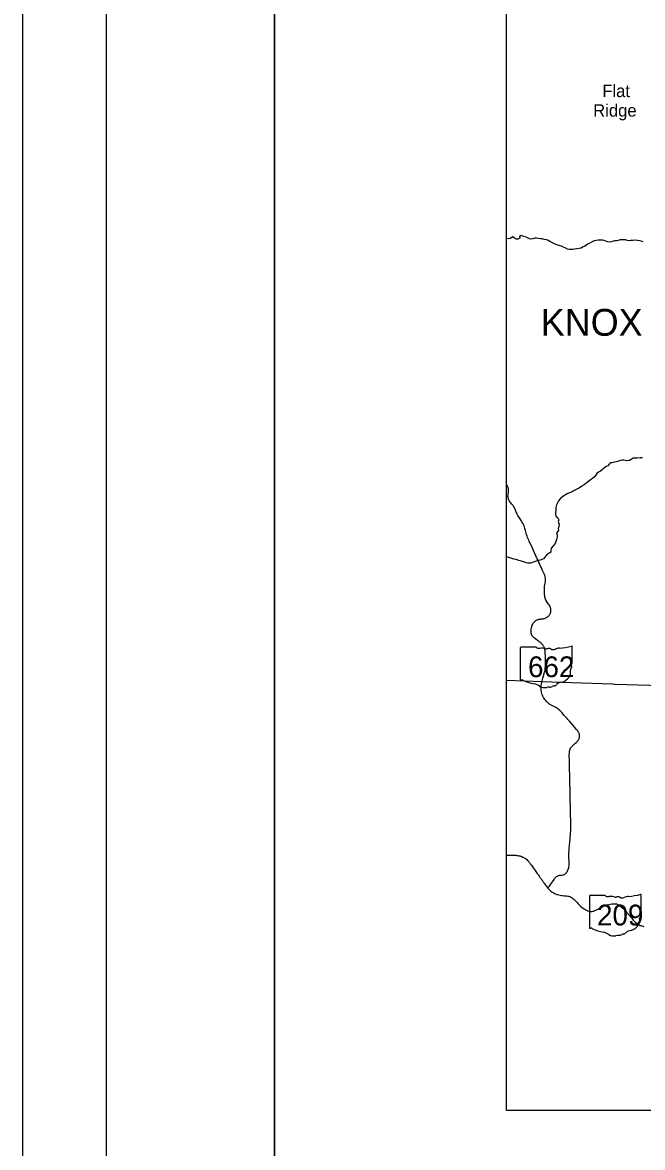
# Model space of a CAD drawing. Extents: x -12.1 to 34, y 0 to 22.
# Drawn here: x 0 to 3.69, y 10.76 to 17.46 of the extents above; entities that cross this region are included whole.
import ezdxf

# ---------------------------------------------------------------- set-up
doc = ezdxf.new("R2010")
doc.units = 0
for name, color, linetype in [('GM_X_Minor_River', 7, 'Continuous'), ('GM_X_State_Location', 7, 'Continuous'), ('GM_X_State_Route', 7, 'Continuous'), ('GM_X_State_Shield', 7, 'Continuous'), ('GM_X_Township', 7, 'Continuous'), ('GM_X_Township_Text', 7, 'Continuous'), ('GM_X_Unincorporated_Text', 7, 'Continuous'), ('SH_Border', 7, 'Continuous'), ('SH_Cut_Line', 7, 'Continuous'), ('SH_Text', 7, 'Continuous')]:
    doc.layers.add(name, color=color, linetype=linetype)

msp = doc.modelspace()

# ---------------------------------------------------------------- linework, layer by layer
at = {"layer": 'GM_X_Minor_River'}
for points in [[(3.6955, 16.1496), (3.6831, 16.153), (3.6742, 16.1565), (3.6617, 16.1581), (3.6454, 16.1597), (3.633, 16.1585), (3.6216, 16.157), (3.6121, 16.1558), (3.6, 16.1586), (3.5911, 16.161), (3.5815, 16.1626), (3.5673, 16.1625), (3.5577, 16.1613), (3.5457, 16.1577), (3.5358, 16.1565), (3.5266, 16.1553), (3.5152, 16.1534), (3.5057, 16.1505), (3.494, 16.1479), (3.4851, 16.1499), (3.473, 16.1537), (3.4623, 16.1572), (3.4531, 16.1588), (3.4396, 16.1601), (3.4265, 16.1593), (3.4141, 16.1574), (3.4024, 16.1548), (3.3908, 16.15), (3.378, 16.1428), (3.3682, 16.1377), (3.3565, 16.1301), (3.347, 16.1244), (3.3343, 16.1178), (3.3251, 16.1128), (3.3134, 16.1098), (3.2851, 16.106), (3.2755, 16.1045), (3.2642, 16.1036), (3.2539, 16.1046), (3.245, 16.1066), (3.2311, 16.1132), (3.2201, 16.1185), (3.209, 16.1233), (3.1998, 16.1268), (3.1894, 16.1295), (3.1805, 16.1319), (3.1713, 16.1357), (3.1624, 16.1402), (3.1517, 16.1462), (3.1399, 16.1524), (3.131, 16.157), (3.1193, 16.1615), (3.1057, 16.1645), (3.0926, 16.1669), (3.0834, 16.1682), (3.0716, 16.1699), (3.0592, 16.1708), (3.05, 16.1714), (3.0376, 16.1681), (3.0263, 16.1662), (3.0174, 16.1672), (3.0031, 16.1752), (2.9914, 16.1801), (2.9793, 16.1842), (2.9679, 16.1866), (2.958, 16.1815), (2.9606, 16.1716), (2.9489, 16.1654), (2.9379, 16.1664), (2.9265, 16.1741), (2.9169, 16.1786), (2.9056, 16.1696), (2.8929, 16.1684), (2.8822, 16.1694), (2.8817, 16.1698)], [(3.5005, 14.8331), (3.4945, 14.8275), (3.4839, 14.8168), (3.4744, 14.8117), (3.4617, 14.802), (3.4519, 14.7937), (3.4399, 14.7847), (3.429, 14.7782), (3.4198, 14.7703), (3.4131, 14.7613), (3.4047, 14.7499), (3.3938, 14.7402), (3.3818, 14.7319), (3.3692, 14.7222), (3.3434, 14.7027), (3.3293, 14.694), (3.3152, 14.6857), (3.3, 14.6778), (3.2849, 14.6691), (3.2722, 14.6622), (3.2559, 14.6556), (3.2428, 14.6491), (3.233, 14.6433), (3.2238, 14.6386), (3.2121, 14.6303), (3.2009, 14.6192), (3.1907, 14.607), (3.1841, 14.5963), (3.1792, 14.5831), (3.1758, 14.5681), (3.1742, 14.5532), (3.1725, 14.5397), (3.1723, 14.5304), (3.1749, 14.5169), (3.186, 14.5064), (3.1918, 14.4947), (3.1897, 14.484), (3.1938, 14.467), (3.1918, 14.4546), (3.188, 14.4425), (3.1902, 14.4311), (3.1797, 14.4178), (3.1837, 14.4076), (3.1838, 14.3969), (3.1807, 14.3852), (3.1787, 14.3756), (3.1742, 14.3652), (3.1704, 14.3538), (3.1605, 14.342), (3.1465, 14.3251), (3.1448, 14.3134), (3.1442, 14.3013), (3.1329, 14.2948), (3.1223, 14.2908), (3.1146, 14.2804), (3.1094, 14.2715), (3.1006, 14.2621), (3.0907, 14.2574), (3.0812, 14.2541), (3.0684, 14.2522), (3.0575, 14.2482), (3.0458, 14.2438), (3.0352, 14.2409), (3.0242, 14.2375), (3.0086, 14.2374), (2.9944, 14.2404), (2.9709, 14.248), (2.9556, 14.2521), (2.9396, 14.2577), (2.925, 14.2611), (2.9133, 14.2649), (2.9012, 14.2686), (2.8887, 14.2724), (2.8817, 14.2737)], [(3.691, 14.8643), (3.6761, 14.8635), (3.6591, 14.8622), (3.6481, 14.8614), (3.6343, 14.8609), (3.6234, 14.8537), (3.6128, 14.8483), (3.6022, 14.8457), (3.5887, 14.8477), (3.5787, 14.8501), (3.5695, 14.8493), (3.5596, 14.847), (3.5486, 14.8437), (3.5337, 14.84), (3.5221, 14.8378), (3.5086, 14.8344), (3.5005, 14.8331)]]:
    msp.add_lwpolyline(points, dxfattribs=at)
at = {"layer": 'GM_X_State_Route'}
for points in [[(3.0917, 13.5312), (3.093, 13.5365), (3.0973, 13.551), (3.1017, 13.5655), (3.1053, 13.579), (3.1077, 13.5886), (3.1085, 13.5922), (3.1105, 13.602), (3.1117, 13.6091), (3.1121, 13.6119), (3.1131, 13.6221), (3.1136, 13.629), (3.1138, 13.6325), (3.114, 13.6406), (3.1138, 13.6569), (3.1132, 13.6675), (3.1126, 13.6865), (3.1119, 13.697), (3.1114, 13.7085), (3.1109, 13.7137), (3.1102, 13.7202), (3.1096, 13.7242), (3.1088, 13.7279), (3.1081, 13.7303), (3.1073, 13.7324), (3.1061, 13.7351), (3.1051, 13.7372), (3.1037, 13.7397), (3.102, 13.7429), (3.1003, 13.7454), (3.0983, 13.748), (3.0955, 13.7514), (3.0925, 13.7548), (3.0882, 13.7591), (3.0846, 13.7622), (3.0801, 13.7658), (3.0763, 13.7686), (3.073, 13.7712), (3.0659, 13.7764), (3.0556, 13.7838), (3.0486, 13.7893), (3.0431, 13.7941), (3.0394, 13.7978), (3.0367, 13.8012), (3.035, 13.8034), (3.0342, 13.8046), (3.0331, 13.8062), (3.0322, 13.8082), (3.0311, 13.8105), (3.0304, 13.8122), (3.0295, 13.8149), (3.0289, 13.8169), (3.0282, 13.8203), (3.0274, 13.825), (3.0271, 13.8295), (3.027, 13.8326), (3.0273, 13.8361), (3.0276, 13.8409), (3.0285, 13.8466), (3.0296, 13.8521), (3.0312, 13.858), (3.0329, 13.8632), (3.0355, 13.8686), (3.0383, 13.8741), (3.0409, 13.8783), (3.0442, 13.883), (3.047, 13.8866), (3.05, 13.8897), (3.0517, 13.8913), (3.0535, 13.8928), (3.0561, 13.8948), (3.0587, 13.8965), (3.062, 13.8984), (3.0655, 13.9), (3.0696, 13.9013), (3.0732, 13.9021), (3.0761, 13.9028), (3.0797, 13.9034), (3.0831, 13.904), (3.0865, 13.9044), (3.0905, 13.9046), (3.0944, 13.9051), (3.0986, 13.9057), (3.1029, 13.9065), (3.107, 13.9074), (3.1114, 13.9087), (3.1159, 13.9108), (3.1197, 13.9126), (3.1231, 13.9147), (3.1256, 13.9164), (3.128, 13.9185), (3.1306, 13.9207), (3.1328, 13.9227), (3.1351, 13.9254), (3.1369, 13.928), (3.1388, 13.9307), (3.1411, 13.9348), (3.1438, 13.9416), (3.1446, 13.9447), (3.1454, 13.9486), (3.1456, 13.9506), (3.1457, 13.9524), (3.1457, 13.9569), (3.1452, 13.9616), (3.1443, 13.9663), (3.1428, 13.9714), (3.141, 13.9762), (3.1382, 13.9824), (3.1346, 13.9885), (3.1301, 13.9951), (3.126, 14.0006), (3.1195, 14.0093), (3.1157, 14.0155), (3.1125, 14.0229), (3.1111, 14.0276), (3.1098, 14.0332), (3.1087, 14.0411), (3.1079, 14.0481), (3.1073, 14.0566), (3.1069, 14.0672), (3.1069, 14.0805), (3.1073, 14.0909), (3.1078, 14.0972), (3.1094, 14.1097), (3.1107, 14.1162), (3.1128, 14.1264), (3.1138, 14.1336), (3.114, 14.1371), (3.1137, 14.1434), (3.1135, 14.1458), (3.1123, 14.1525), (3.1111, 14.1565), (3.109, 14.1632), (3.1065, 14.1695), (3.1027, 14.1777), (3.0954, 14.1938), (3.0914, 14.2023), (3.0889, 14.2084), (3.0844, 14.2184), (3.0822, 14.2231), (3.0796, 14.2286), (3.0779, 14.2326), (3.0774, 14.2336), (3.074, 14.2409), (3.0714, 14.2467), (3.069, 14.2519), (3.0669, 14.2567), (3.0644, 14.2619), (3.0564, 14.28), (3.048, 14.2986), (3.036, 14.3251), (3.0311, 14.3357), (3.0272, 14.3435), (3.017, 14.3655), (3.0137, 14.3728), (3.0101, 14.3811), (3.007, 14.389), (3.004, 14.3973), (3.0007, 14.4077), (2.9945, 14.4308), (2.9911, 14.4427), (2.9885, 14.451), (2.9856, 14.4592), (2.9821, 14.4668), (2.9779, 14.475), (2.9734, 14.4833), (2.969, 14.4905), (2.9582, 14.5055), (2.9529, 14.5134), (2.9487, 14.5208), (2.9451, 14.5278), (2.9423, 14.5337), (2.9397, 14.54), (2.9351, 14.5525), (2.9311, 14.5618), (2.9271, 14.5696), (2.9231, 14.576), (2.9202, 14.5797), (2.9132, 14.5881), (2.9051, 14.5984), (2.8992, 14.606), (2.8968, 14.61), (2.8951, 14.6134), (2.893, 14.6189), (2.8918, 14.623), (2.8906, 14.6293), (2.8901, 14.6356), (2.8904, 14.6425), (2.8913, 14.6487), (2.8924, 14.6564), (2.8932, 14.6644), (2.8935, 14.6691), (2.8933, 14.6731), (2.8929, 14.6785), (2.892, 14.6827), (2.8907, 14.6871), (2.8888, 14.6919), (2.8867, 14.6959), (2.8827, 14.7022), (2.8817, 14.7033)], [(3.1273, 12.3022), (3.1283, 12.3032), (3.13, 12.305), (3.1315, 12.3068), (3.1367, 12.3135), (3.1433, 12.3232), (3.1548, 12.3399), (3.1642, 12.3532), (3.1694, 12.3602), (3.1728, 12.3643), (3.1765, 12.368), (3.1796, 12.3707), (3.183, 12.3732), (3.1867, 12.3753), (3.19, 12.3768), (3.1923, 12.3774), (3.1939, 12.3777), (3.1967, 12.3781), (3.1996, 12.3785), (3.2022, 12.3786), (3.2067, 12.3788), (3.2115, 12.3793), (3.2176, 12.3804), (3.2203, 12.3811), (3.2216, 12.3816), (3.2238, 12.3827), (3.2284, 12.3852), (3.23, 12.3862), (3.2321, 12.388), (3.2346, 12.39), (3.236, 12.3914), (3.2385, 12.3944), (3.2416, 12.3995), (3.2444, 12.404), (3.2492, 12.4148), (3.2513, 12.4213), (3.2527, 12.4271), (3.2538, 12.434), (3.2543, 12.4413), (3.2542, 12.4493), (3.2538, 12.4617), (3.2526, 12.4831), (3.2527, 12.4955), (3.2529, 12.5057), (3.2532, 12.5144), (3.2541, 12.5264), (3.255, 12.5405), (3.2564, 12.5558), (3.258, 12.5766), (3.2595, 12.5911), (3.2628, 12.6297), (3.2636, 12.6441), (3.2642, 12.6523), (3.2644, 12.6608), (3.2644, 12.6666), (3.2646, 12.6716), (3.2647, 12.6784), (3.2645, 12.6877), (3.2643, 12.6935), (3.2638, 12.708), (3.2634, 12.7156), (3.2631, 12.7261), (3.2631, 12.7343), (3.2631, 12.7447), (3.2628, 12.7574), (3.2627, 12.772), (3.2617, 12.7953), (3.2609, 12.8174), (3.2605, 12.8314), (3.2601, 12.8611), (3.2599, 12.8762), (3.2596, 12.8931), (3.2589, 12.9186), (3.2585, 12.932), (3.2582, 12.9442), (3.2581, 12.9488), (3.2579, 12.9558), (3.2577, 12.9634), (3.2573, 12.9797), (3.2567, 13.0035), (3.2561, 13.0315), (3.2559, 13.0489), (3.2555, 13.0693), (3.2551, 13.0862), (3.255, 13.0966), (3.2553, 13.106), (3.2558, 13.1124), (3.2566, 13.1188), (3.2578, 13.124), (3.2593, 13.1284), (3.2611, 13.1328), (3.263, 13.1365), (3.2652, 13.1399), (3.2683, 13.1436), (3.2717, 13.1474), (3.2763, 13.1517), (3.2859, 13.1602), (3.2969, 13.1697), (3.3036, 13.1761), (3.3074, 13.1804), (3.3099, 13.1849), (3.3118, 13.1885), (3.313, 13.1912), (3.3139, 13.1944), (3.315, 13.1979), (3.3156, 13.2008), (3.3162, 13.2046), (3.3163, 13.2074), (3.3162, 13.2097), (3.3158, 13.2134), (3.3153, 13.2171), (3.3146, 13.2196), (3.3139, 13.2221), (3.3131, 13.2241), (3.3121, 13.2267), (3.3103, 13.2303), (3.3088, 13.2329), (3.3074, 13.2351), (3.3053, 13.2381), (3.3035, 13.2405), (3.2988, 13.2461), (3.2869, 13.26), (3.2803, 13.2679), (3.2702, 13.2792), (3.2558, 13.2954), (3.2462, 13.3061), (3.2402, 13.3129), (3.2304, 13.3244), (3.2234, 13.3324), (3.2126, 13.3451), (3.205, 13.3536), (3.2011, 13.3575), (3.198, 13.3602), (3.1914, 13.3659), (3.1879, 13.3686), (3.1853, 13.3705), (3.1803, 13.3735), (3.1742, 13.3768), (3.1588, 13.3846), (3.1475, 13.3907), (3.1427, 13.3935), (3.1397, 13.3955), (3.137, 13.3973), (3.1348, 13.3989), (3.1327, 13.4005), (3.1303, 13.4025), (3.1285, 13.404), (3.1272, 13.4052), (3.1249, 13.4075), (3.1203, 13.412), (3.1153, 13.418), (3.1102, 13.4249), (3.1057, 13.4313), (3.1018, 13.4376), (3.0979, 13.4448), (3.0952, 13.4508), (3.0922, 13.4583), (3.09, 13.4656), (3.0889, 13.471), (3.0877, 13.4786), (3.0871, 13.4861), (3.0869, 13.4937), (3.0871, 13.5018), (3.0878, 13.5098), (3.0889, 13.5179), (3.0906, 13.527), (3.0917, 13.5312)], [(2.8817, 12.4978), (2.8837, 12.4978), (2.8866, 12.4978), (2.8942, 12.4978), (2.9, 12.4978), (2.9064, 12.4979), (2.9121, 12.4979), (2.9185, 12.4978), (2.9214, 12.4977), (2.9284, 12.4976), (2.937, 12.4973), (2.9416, 12.4969), (2.9462, 12.4964), (2.9495, 12.4959), (2.9551, 12.4948), (2.9602, 12.4936), (2.9636, 12.4927), (2.966, 12.4919), (2.969, 12.4907), (2.9727, 12.4893), (2.9785, 12.4866), (2.9825, 12.4846), (2.9873, 12.4819), (2.9914, 12.4795), (2.9949, 12.4771), (2.9972, 12.4752), (3.0017, 12.4716), (3.0071, 12.4664), (3.0097, 12.4635), (3.0123, 12.4604), (3.0177, 12.4536), (3.0205, 12.4499), (3.0225, 12.4471), (3.0236, 12.4457), (3.025, 12.4439), (3.0275, 12.4407), (3.0293, 12.4384), (3.0341, 12.4318), (3.0404, 12.4228), (3.0461, 12.4147), (3.0491, 12.4105), (3.056, 12.4004), (3.0636, 12.3894), (3.0674, 12.3842), (3.0691, 12.3819), (3.0718, 12.3781), (3.076, 12.3726), (3.0784, 12.3692), (3.0807, 12.3659), (3.0813, 12.365), (3.0844, 12.3608), (3.0874, 12.3565), (3.0894, 12.3536), (3.0901, 12.3527), (3.0928, 12.349), (3.0957, 12.3447), (3.098, 12.3413), (3.1018, 12.3362), (3.1041, 12.3328), (3.1064, 12.3295), (3.1071, 12.3285), (3.1105, 12.3238), (3.1139, 12.3191), (3.117, 12.3149), (3.1206, 12.3103), (3.1235, 12.3066), (3.1273, 12.3022), (3.1288, 12.3004), (3.1342, 12.2943), (3.1393, 12.2891), (3.1449, 12.2842), (3.1536, 12.2783), (3.1584, 12.2753), (3.161, 12.2737), (3.1672, 12.2703), (3.1725, 12.2677), (3.177, 12.2658), (3.18, 12.2646), (3.185, 12.2628), (3.1924, 12.2608), (3.2001, 12.2589), (3.2082, 12.2576), (3.2143, 12.257), (3.2258, 12.2562), (3.2385, 12.2557), (3.2457, 12.2547), (3.2498, 12.254), (3.2538, 12.2528), (3.2577, 12.2512), (3.2625, 12.2492), (3.2674, 12.2467), (3.2716, 12.2439), (3.2757, 12.2408), (3.2814, 12.2359), (3.2855, 12.2317), (3.2895, 12.2277), (3.301, 12.2153), (3.3086, 12.2072), (3.3162, 12.1999), (3.3245, 12.1926), (3.3322, 12.1864), (3.3402, 12.1804), (3.3474, 12.1755), (3.3533, 12.1721), (3.3567, 12.1701), (3.3608, 12.1682), (3.364, 12.1668), (3.3696, 12.1649), (3.3746, 12.1636), (3.3798, 12.1628), (3.3842, 12.1625), (3.3877, 12.1626), (3.3918, 12.1631), (3.3968, 12.164), (3.4005, 12.1651), (3.4036, 12.1662), (3.4073, 12.1678), (3.4136, 12.1707), (3.4217, 12.1747), (3.4442, 12.187), (3.4549, 12.1921), (3.4626, 12.1954), (3.4652, 12.1964), (3.4717, 12.1985), (3.4812, 12.2014), (3.4898, 12.2035), (3.4977, 12.2053), (3.5081, 12.2072), (3.5144, 12.208), (3.5199, 12.2084), (3.5261, 12.2084), (3.5321, 12.208), (3.5362, 12.2073), (3.5407, 12.206), (3.5449, 12.2043), (3.5496, 12.2019), (3.5544, 12.1992), (3.5583, 12.1964), (3.5625, 12.1929), (3.5738, 12.1825), (3.5792, 12.177), (3.5856, 12.1698), (3.5954, 12.1587), (3.6112, 12.1402), (3.6267, 12.122), (3.6361, 12.1114), (3.6437, 12.1031), (3.6499, 12.0972), (3.6554, 12.0926), (3.6604, 12.0889), (3.6642, 12.0864), (3.6712, 12.0826), (3.6775, 12.0799), (3.6812, 12.0786), (3.6874, 12.0764), (3.6981, 12.0731)]]:
    msp.add_lwpolyline(points, dxfattribs=at)
at = {"layer": 'GM_X_State_Shield'}
for p, q in [((2.9635, 13.7322), (2.9635, 13.5446)), ((3.057, 13.7354), (2.9665, 13.7354)), ((3.2725, 13.642), (3.2725, 13.7401)), ((3.2724, 13.642), (3.2725, 13.642)), ((3.6838, 12.1636), (3.6838, 12.2617)), ((3.3749, 12.2539), (3.3749, 12.0662)), ((3.4684, 12.2571), (3.3779, 12.2571)), ((3.6838, 12.1636), (3.6838, 12.1636))]:
    msp.add_line(p, q, dxfattribs=at)
for centre, major_axis, start_param, end_param in [((2.967, 13.7326), (0.00358, 0), 1.712693, 3.28349), ((3.0786, 13.7572), (0.0347, 0), 4.042523, 4.731795), ((3.1624, 13.9912), (0.3277, 0), 4.814394, 5.042369), ((3.269, 13.7405), (0.00344, 0), 6.141152, 7.989035), ((3.0901, 13.6301), (0.1246, 0), 1.404758, 1.657858), ((3.1184, 13.7336), (0.01, 0), 3.836095, 5.185415), ((3.1331, 13.7119), (0.0208, 0), 0.950623, 2.079405), ((3.16, 13.7417), (0.0251, 0), 4.081561, 5.145723), ((3.2042, 13.6781), (0.0659, 0), 1.699011, 2.107814), ((3.1808, 13.5884), (0.082, 0), 5.101752, 6.440018), ((3.2848, 13.6009), (0.0232, 0), 2.387724, 3.262537), ((3.2717, 13.6348), (0.00532, 0), 1.883978, 3.671073), ((3.2378, 13.6223), (0.032, 0), 5.934695, 6.695948), ((3.2688, 13.6416), (0.00368, 0), 5.05454, 6.418171), ((2.9671, 13.5442), (0.00361, 0), 3.00124, 4.508301), ((2.9676, 13.5634), (0.0276, 0), 4.665946, 4.897461), ((2.9732, 13.5338), (0.00994, 0), 0.519207, 1.627899), ((3.0987, 13.7023), (0.2366, 0), 4.195997, 4.488961), ((3.0282, 13.4603), (0.074, 0), 0.823519, 1.323587), ((3.1082, 13.5329), (0.047, 0), 4.026481, 4.996735), ((3.1354, 13.468), (0.0386, 0), 1.495662, 1.94098), ((3.1388, 13.5188), (0.025, 0), 4.691044, 5.507374), ((3.1615, 13.5006), (0.00705, 0), 1.147584, 2.315152), ((3.1584, 13.5264), (0.0265, 0), 4.937069, 5.64225), ((3.2153, 13.4919), (0.0449, 0), 1.647645, 2.488434), ((3.5738, 12.5129), (0.3277, 0), 4.814394, 5.042369), ((3.6804, 12.2621), (0.00344, 0), 6.141152, 7.989035), ((3.3784, 12.2543), (0.00358, 0), 1.712693, 3.28349), ((3.4899, 12.2789), (0.0347, 0), 4.042523, 4.731795), ((3.5014, 12.1518), (0.1246, 0), 1.404758, 1.657858), ((3.5297, 12.2552), (0.01, 0), 3.836095, 5.185415), ((3.5444, 12.2335), (0.0208, 0), 0.950623, 2.079405), ((3.5713, 12.2633), (0.0251, 0), 4.081561, 5.145723), ((3.6156, 12.1998), (0.0659, 0), 1.699011, 2.107814), ((3.6962, 12.1225), (0.0232, 0), 2.387724, 3.262537), ((3.683, 12.1564), (0.00532, 0), 1.883978, 3.671073), ((3.6492, 12.144), (0.032, 0), 5.934695, 6.695948), ((3.6802, 12.1632), (0.00368, 0), 5.05454, 6.418171), ((3.3784, 12.0658), (0.00361, 0), 3.00124, 4.508301), ((3.379, 12.085), (0.0276, 0), 4.665946, 4.897461), ((3.3846, 12.0554), (0.00994, 0), 0.519207, 1.627899), ((3.5101, 12.224), (0.2366, 0), 4.195997, 4.488961), ((3.5921, 12.11), (0.082, 0), 5.101752, 6.440018), ((3.4395, 11.982), (0.074, 0), 0.823519, 1.323587), ((3.5196, 12.0545), (0.047, 0), 4.026481, 4.996735), ((3.5467, 11.9896), (0.0386, 0), 1.495662, 1.94098), ((3.5502, 12.0404), (0.025, 0), 4.691044, 5.507374), ((3.5728, 12.0223), (0.00705, 0), 1.147584, 2.315152), ((3.5698, 12.0481), (0.0265, 0), 4.937069, 5.64225), ((3.6267, 12.0136), (0.0449, 0), 1.647645, 2.488434)]:
    msp.add_ellipse(centre, major_axis=major_axis, ratio=0.8, start_param=start_param, end_param=end_param, dxfattribs=at)
at = {"layer": 'GM_X_Township'}
msp.add_lwpolyline([(2.8817, 13.5392), (3.0915, 13.5317), (3.5107, 13.5177), (3.513, 13.5176), (3.5238, 13.517), (3.5287, 13.5169), (4.3507, 13.4926), (5.621, 13.4542), (6.0948, 13.439)], dxfattribs=at)
at = {"layer": 'SH_Border'}
for points in [[(0.5, 21.5), (1.5, 21.5), (1.5, 0.5), (0.5, 0.5)], [(1.5, 21.5), (33.5, 21.5), (33.5, 0.5), (1.5, 0.5)]]:
    msp.add_lwpolyline(points, close=True, dxfattribs=at)
at = {"layer": 'SH_Cut_Line'}
msp.add_lwpolyline([(0, 0), (34, 0), (34, 22), (0, 22)], close=True, dxfattribs=at)
at = {"layer": 'SH_Text'}
msp.add_lwpolyline([(2.8817, 20.3063), (10.5897, 20.3063), (10.5897, 10.9773), (2.8817, 10.9773)], close=True, dxfattribs=at)

# ---------------------------------------------------------------- texts
at = {"layer": 'GM_X_State_Location'}
msp.add_text('662', height=0.000178, rotation=0.00001, dxfattribs=at).set_placement((3.0518, 13.613))
for s in ['s', 'r']:
    msp.add_text(s, height=0.000178, dxfattribs=at).set_placement((3.1145, 13.6259))
at = {"layer": 'GM_X_State_Shield'}
for s, p in [('662', (3.0094, 13.5578)), ('209', (3.4203, 12.0795))]:
    msp.add_text(s, height=0.1236, dxfattribs=at).set_placement(p)
at = {"layer": 'GM_X_Township_Text'}
msp.add_text('KNOX', height=0.1598, rotation=0.00001, dxfattribs=at).set_placement((3.0857, 15.5905))
at = {"layer": 'GM_X_Unincorporated_Text'}
for s, p in [('Flat', (3.4512, 17.0115)), ('Ridge', (3.3973, 16.8951))]:
    msp.add_text(s, height=0.07404, rotation=0.00001, dxfattribs=at).set_placement(p)

doc.saveas('drawing.dxf')
